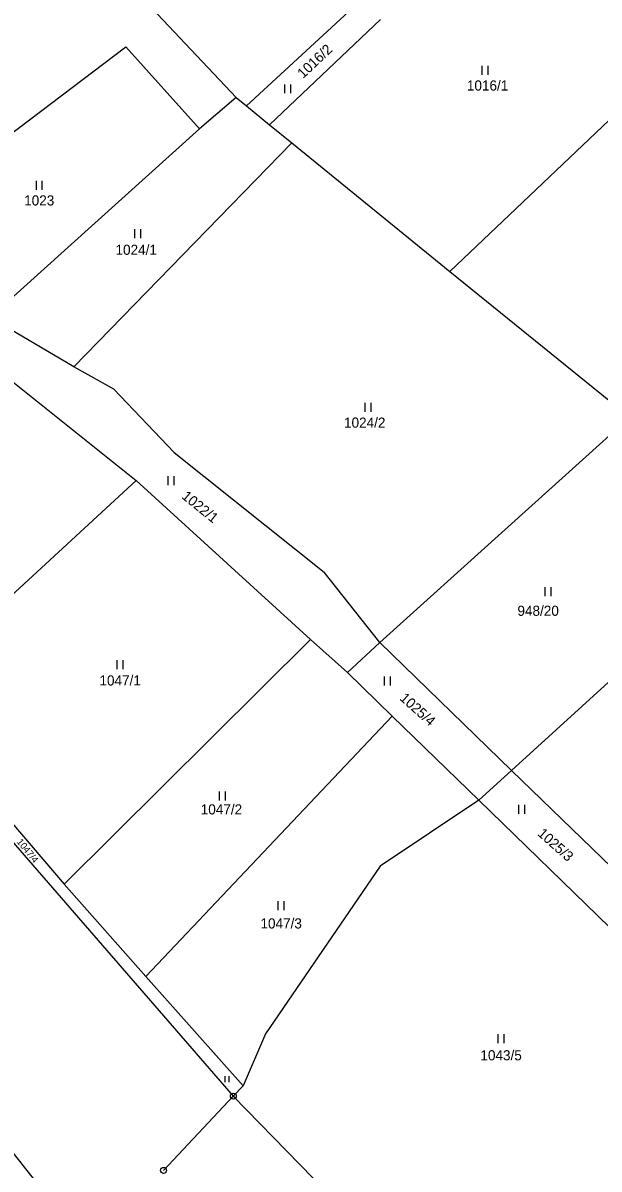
# Model space of a CAD drawing. Extents: x -445050 to -440454, y -1134563 to -1129741.
# Drawn here: x -440973 to -440876.2, y -1131580.2 to -1131387.8 of the extents above; entities that cross this region are included whole.
import ezdxf

# ---------------------------------------------------------------- set-up
doc = ezdxf.new("R2010")
doc.units = 0
for name, color, linetype in [('Vrstva 1', 7, 'Continuous'), ('Vrstva 18', 7, 'Continuous'), ('Vrstva 24', 7, 'Continuous'), ('Vrstva 25', 7, 'Continuous'), ('Vrstva 6', 7, 'Continuous')]:
    doc.layers.add(name, color=color, linetype=linetype)

msp = doc.modelspace()

# ---------------------------------------------------------------- linework, layer by layer
at = {"layer": 'Vrstva 1'}
for points in [[(-440964.42, -1131445.54), (-440978.54, -1131437.22)], [(-440957.74, -1131449.28), (-440964.42, -1131445.54)], [(-440957.74, -1131449.28), (-440947.58, -1131459.9)], [(-440947.58, -1131459.9), (-440922.39, -1131479.99)], [(-440913.06, -1131491.81), (-440922.39, -1131479.99)], [(-440890.95, -1131513.33), (-440913.06, -1131491.81)], [(-440869.01, -1131534.5), (-440890.95, -1131513.33)], [(-440949.38, -1131580.44), (-440937.66, -1131567.98)], [(-440937.66, -1131567.98), (-440904.13, -1131602.39)]]:
    msp.add_lwpolyline(points, dxfattribs=at)
at = {"layer": 'Vrstva 24'}
for centre, radius in [((-440937.66, -1131567.98), 0.5), ((-440937.66, -1131567.98), 0.1), ((-440949.38, -1131580.44), 0.5)]:
    msp.add_circle(centre, radius, dxfattribs=at)
at = {"layer": 'Vrstva 25'}
for p, q in [((-440895.85, -1131396.48), (-440895.85, -1131394.98)), ((-440894.85, -1131396.48), (-440894.85, -1131394.98)), ((-440929.03, -1131399.6), (-440929.03, -1131398.1)), ((-440928.03, -1131399.6), (-440928.03, -1131398.1)), ((-440970.73, -1131415.82), (-440970.73, -1131414.32)), ((-440969.73, -1131415.82), (-440969.73, -1131414.32)), ((-440954.21, -1131423.9), (-440954.21, -1131422.4)), ((-440953.21, -1131423.9), (-440953.21, -1131422.4)), ((-440915.54, -1131453.09), (-440915.54, -1131451.59)), ((-440914.54, -1131453.09), (-440914.54, -1131451.59)), ((-440948.59, -1131465.37), (-440948.59, -1131463.87)), ((-440947.59, -1131465.37), (-440947.59, -1131463.87)), ((-440885.3, -1131484.04), (-440885.3, -1131482.54)), ((-440884.3, -1131484.04), (-440884.3, -1131482.54)), ((-440957.18, -1131496.3), (-440957.18, -1131494.8)), ((-440956.18, -1131496.3), (-440956.18, -1131494.8)), ((-440912.26, -1131499.02), (-440912.26, -1131497.52)), ((-440911.26, -1131499.02), (-440911.26, -1131497.52)), ((-440939.98, -1131518.34), (-440939.98, -1131516.84)), ((-440938.98, -1131518.34), (-440938.98, -1131516.84)), ((-440889.72, -1131520.56), (-440889.72, -1131519.06)), ((-440888.72, -1131520.56), (-440888.72, -1131519.06)), ((-440930.11, -1131536.74), (-440930.11, -1131535.24)), ((-440929.11, -1131536.74), (-440929.11, -1131535.24)), ((-440893.18, -1131559.09), (-440893.18, -1131557.59)), ((-440892.18, -1131559.09), (-440892.18, -1131557.59)), ((-440939.04, -1131565.61), (-440939.04, -1131564.6)), ((-440938.36, -1131565.61), (-440938.36, -1131564.6))]:
    msp.add_line(p, q, dxfattribs=at)
at = {"layer": 'Vrstva 6'}
for points in [[(-440956.08, -1131380.19), (-440937.17, -1131400.3)], [(-440916.12, -1131383.84), (-440935.44, -1131401.71)], [(-440912.96, -1131387.19), (-440931.56, -1131404.87)], [(-440856.68, -1131387.16), (-440901.29, -1131429.5)], [(-440993.68, -1131420.5), (-440955.71, -1131391.77)], [(-440955.71, -1131391.77), (-440943.33, -1131405.56)], [(-440937.17, -1131400.3), (-440943.33, -1131405.56)], [(-440937.17, -1131400.3), (-440935.44, -1131401.71)], [(-440935.44, -1131401.71), (-440931.56, -1131404.87)], [(-440943.33, -1131405.56), (-440978.54, -1131437.22)], [(-440931.56, -1131404.87), (-440927.81, -1131407.92)], [(-440927.81, -1131407.92), (-440964.42, -1131445.54)], [(-440927.81, -1131407.92), (-440901.29, -1131429.5)], [(-440901.29, -1131429.5), (-440871.06, -1131453.95)], [(-440983.11, -1131441.31), (-440953.97, -1131464.61)], [(-440871.06, -1131453.95), (-440913.06, -1131491.81)], [(-440953.97, -1131464.61), (-440993.13, -1131500.7)], [(-440953.97, -1131464.61), (-440924.7, -1131491.32)], [(-440924.7, -1131491.32), (-440966.07, -1131532.36)], [(-440924.7, -1131491.32), (-440918.49, -1131496.86)], [(-440913.06, -1131491.81), (-440918.49, -1131496.86)], [(-440918.49, -1131496.86), (-440910.96, -1131504.18)], [(-440890.95, -1131513.33), (-440871.61, -1131495.69)], [(-440993.13, -1131500.7), (-440966.07, -1131532.36)], [(-440994.79, -1131502.21), (-440937.66, -1131567.98)], [(-440910.96, -1131504.18), (-440952.33, -1131547.9)], [(-440910.96, -1131504.18), (-440896.43, -1131518.31)], [(-440890.95, -1131513.33), (-440896.43, -1131518.31)], [(-440896.43, -1131518.31), (-440913.03, -1131529.34)], [(-440896.43, -1131518.31), (-440874.46, -1131539.68)], [(-440913.03, -1131529.34), (-440932.28, -1131557.49)], [(-440952.33, -1131547.9), (-440966.07, -1131532.36)], [(-440936.03, -1131566.25), (-440952.33, -1131547.9)], [(-440932.28, -1131557.49), (-440936.03, -1131566.25)], [(-440937.66, -1131567.98), (-440936.03, -1131566.25)], [(-440983.23, -1131566.7), (-440965.2, -1131589.5)]]:
    msp.add_lwpolyline(points, dxfattribs=at)

# ---------------------------------------------------------------- texts
at = {"layer": 'Vrstva 18'}
for s, height, rotation, p in [('1016/2', 1.7, 43.4007, (-440925.94, -1131397.2)), ('1022/1', 1.7, 320.9607, (-440946.45, -1131467.49)), ('1025/4', 1.7, 318.1743, (-440909.84, -1131501.34)), ('1025/3', 1.7, 318.2481, (-440886.69, -1131524.08)), ('1047/4', 1.14, 308.7227, (-440974.09, -1131525.3))]:
    msp.add_text(s, height=height, rotation=rotation, dxfattribs=at).set_placement(p)
for s, p in [('1016/1', (-440898.44, -1131399.14)), ('1023', (-440972.78, -1131418.43)), ('1024/1', (-440957.44, -1131426.72)), ('1024/2', (-440919.07, -1131455.74)), ('948/20', (-440889.95, -1131487.33)), ('1047/1', (-440960.14, -1131499.03)), ('1047/2', (-440943.13, -1131520.68)), ('1047/3', (-440933.1, -1131539.83)), ('1043/5', (-440896.17, -1131561.97))]:
    msp.add_text(s, height=1.7, dxfattribs=at).set_placement(p)

doc.saveas('drawing.dxf')
